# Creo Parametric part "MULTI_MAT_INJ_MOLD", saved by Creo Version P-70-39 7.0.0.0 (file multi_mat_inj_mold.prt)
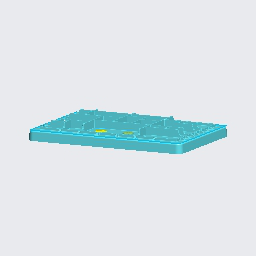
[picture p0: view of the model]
Units: millimeter Kilogram Sec (mmKs); MM, KILOGRAM, SECS
Materials in the file: PBT-GF, SILICONE_RUBBER

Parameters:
  PTC_MASTER_MATERIAL = "PTC_SYSTEM_MTRL_PROPS"
  GRANTA_DATALINK_VERSION = "5"
  GRANTA_DATABASE_KEY = "Granta_Typical_Materials"
  GRANTA_IDENTITY_GUID = "313e4ad7-cf3c-4817-b993-b3f9b776e9b8"
  GRANTA_VERSION_GUID = "513b4d9c-127e-4c03-b132-1654ae4c391c"
  GRANTA_MODEL_REFERENCE = "00000000-0000-0000-0000-000000000000"

Other parameters: TEST, MASS

Created from: MB_MULTIMAT_INJ_MOLDED_DEMO.PRT

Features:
  1. datum plane "RIGHT"
  2. datum plane "TOP"
  3. datum plane "FRONT"
  4. coordinate system
  5. group "LOCAL_GROUP"
  6. curve
  7. protrusion
  8. protrusion
  9. datum plane "DTM1"
  10. datum plane "DTM2"
  11. curve
  12. protrusion
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
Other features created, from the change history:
  feature "Internal Volume 1"
  patch "Solidify 1"
  feature "Internal Volume 2"
  feature "Remove Body 1"
  feature "Published Geometry id 44484"
  round "Round 9"
  round "Round 10"
  datum plane "DTM3"
  planar section "A"
  feature "MASS_PROP_1"
  feature "MASS_PROP_OVERMOLD1"
  group "LOCAL_GROUP"
  group "LOCAL_GROUP_1"

Other named items: CUTOUT_PORT_W_OVERM_TYPE_A, MASS_PROP_HOUSING, CUTOUT_OVERMOLD_TYPE_B, YZ, TOP_PLUS_HEIGHT, BOTTOM_PLUS_HEIGHT, XSEC_REF, CS0, HOUSING, OVERMOLD1, WITH_OVERMOLD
